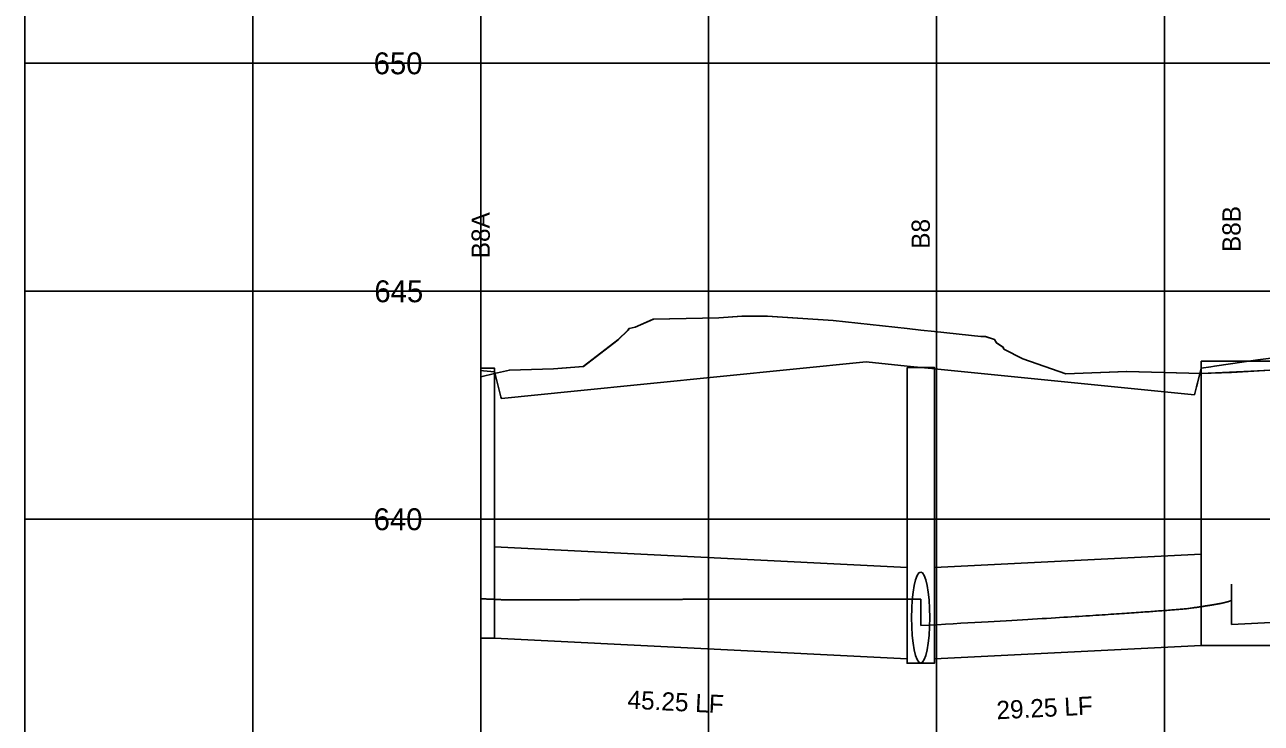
# Model space of a CAD drawing. Extents: x 2254979 to 2278074, y 13790855 to 13792793.
# Drawn here: x 2277749.4 to 2277885, y 13792568.9 to 13792645.5 of the extents above; entities that cross this region are included whole.
import ezdxf

# ---------------------------------------------------------------- set-up
doc = ezdxf.new("R2010")
doc.units = 0
for name, color, linetype in [('blank4', 7, 'Continuous'), ('BORD_grid_bottom_major_5int', 7, 'Continuous'), ('D_DRN_PROF_HGL', 7, 'Continuous'), ('D_PROF_1', 7, 'Continuous'), ('D_PROF_NOTES_1', 7, 'Continuous'), ('Default', 7, 'Continuous'), ('Drain_PipeInside', 7, 'Continuous'), ('E_Terrain', 7, 'Continuous'), ('Inlet', 7, 'Continuous'), ('z - Construction', 7, 'Continuous')]:
    doc.layers.add(name, color=color, linetype=linetype)

msp = doc.modelspace()

# ---------------------------------------------------------------- linework, layer by layer
at = {"layer": 'blank4'}
msp.add_lwpolyline([(2277799.4, 13792541.27), (2277799.4, 13792641.27), (2277979.76, 13792641.27), (2277979.76, 13792541.27)], close=True, dxfattribs=at)
at = {"layer": 'BORD_grid_bottom_major_5int'}
for p, q in [((2277749.4, 13792491.27), (2277749.4, 13792791.27)), ((2277774.4, 13792491.27), (2277774.4, 13792791.27)), ((2277799.4, 13792491.27), (2277799.4, 13792791.27)), ((2277824.4, 13792491.27), (2277824.4, 13792791.27)), ((2277849.4, 13792491.27), (2277849.4, 13792791.27)), ((2277874.4, 13792491.27), (2277874.4, 13792791.27)), ((2277749.4, 13792641.27), (2278074.4, 13792641.27)), ((2277749.4, 13792616.27), (2278074.4, 13792616.27)), ((2277749.4, 13792591.27), (2278074.4, 13792591.27))]:
    msp.add_line(p, q, dxfattribs=at)
at = {"layer": 'D_DRN_PROF_HGL'}
for p, q in [((2277881.73, 13792584.14), (2277881.73, 13792579.73)), ((2277847.65, 13792582.52), (2277847.65, 13792579.61))]:
    msp.add_line(p, q, dxfattribs=at)
for points in [[(2277847.65, 13792579.61), (2277848.55, 13792579.66), (2277849.47, 13792579.71), (2277850.36, 13792579.76), (2277851.22, 13792579.81), (2277852.04, 13792579.86), (2277852.83, 13792579.9), (2277853.59, 13792579.94), (2277854.32, 13792579.99), (2277855.03, 13792580.03), (2277855.72, 13792580.07), (2277856.38, 13792580.1), (2277857.02, 13792580.14), (2277857.63, 13792580.18), (2277858.23, 13792580.21), (2277858.81, 13792580.25), (2277859.38, 13792580.28), (2277859.92, 13792580.31), (2277860.45, 13792580.34), (2277860.97, 13792580.37), (2277861.46, 13792580.4), (2277861.95, 13792580.43), (2277862.42, 13792580.46), (2277862.88, 13792580.49), (2277863.33, 13792580.52), (2277863.76, 13792580.54), (2277864.19, 13792580.57), (2277864.6, 13792580.6), (2277865, 13792580.62), (2277865.39, 13792580.64), (2277865.77, 13792580.67), (2277866.15, 13792580.69), (2277866.51, 13792580.72), (2277866.86, 13792580.74), (2277867.21, 13792580.76), (2277867.55, 13792580.78), (2277867.88, 13792580.8), (2277868.2, 13792580.83), (2277868.51, 13792580.85), (2277868.82, 13792580.87), (2277869.12, 13792580.89), (2277869.41, 13792580.91), (2277869.7, 13792580.93), (2277869.98, 13792580.94), (2277870.25, 13792580.96), (2277870.52, 13792580.98), (2277870.78, 13792581), (2277871.04, 13792581.02), (2277871.29, 13792581.03), (2277871.54, 13792581.05), (2277871.78, 13792581.07), (2277872.01, 13792581.09), (2277872.24, 13792581.1), (2277872.47, 13792581.12), (2277872.69, 13792581.13), (2277872.9, 13792581.15), (2277873.11, 13792581.17), (2277873.32, 13792581.18), (2277873.52, 13792581.2), (2277873.72, 13792581.21), (2277873.91, 13792581.23), (2277874.1, 13792581.24), (2277874.29, 13792581.25), (2277874.47, 13792581.27), (2277874.65, 13792581.28), (2277874.83, 13792581.3), (2277875, 13792581.31), (2277875.17, 13792581.32), (2277875.33, 13792581.34), (2277875.49, 13792581.35), (2277875.65, 13792581.36), (2277875.81, 13792581.38), (2277875.96, 13792581.39), (2277876.11, 13792581.4), (2277876.25, 13792581.41), (2277876.39, 13792581.42), (2277876.53, 13792581.44), (2277876.67, 13792581.45), (2277876.81, 13792581.46), (2277876.94, 13792581.47), (2277877.07, 13792581.49), (2277877.19, 13792581.51), (2277877.32, 13792581.53), (2277877.44, 13792581.54), (2277877.56, 13792581.56), (2277877.67, 13792581.58), (2277877.79, 13792581.59), (2277877.9, 13792581.61), (2277878.01, 13792581.63), (2277878.11, 13792581.64), (2277878.22, 13792581.66), (2277878.32, 13792581.67), (2277878.42, 13792581.69), (2277878.52, 13792581.7), (2277878.62, 13792581.72), (2277878.71, 13792581.73), (2277878.8, 13792581.75), (2277878.89, 13792581.76), (2277878.98, 13792581.77), (2277879.07, 13792581.79), (2277879.15, 13792581.8), (2277879.24, 13792581.81), (2277879.32, 13792581.83), (2277879.4, 13792581.84), (2277879.47, 13792581.85), (2277879.55, 13792581.86), (2277879.62, 13792581.88), (2277879.7, 13792581.89), (2277879.77, 13792581.9), (2277879.84, 13792581.91), (2277879.9, 13792581.93), (2277879.97, 13792581.94), (2277880.03, 13792581.95), (2277880.1, 13792581.96), (2277880.16, 13792581.97), (2277880.22, 13792581.98), (2277880.28, 13792581.99), (2277880.33, 13792582), (2277880.39, 13792582.01), (2277880.44, 13792582.02), (2277880.5, 13792582.03), (2277880.55, 13792582.04), (2277880.6, 13792582.05), (2277880.65, 13792582.06), (2277880.69, 13792582.07), (2277880.74, 13792582.08), (2277880.78, 13792582.09), (2277880.83, 13792582.1), (2277880.87, 13792582.11), (2277880.91, 13792582.12), (2277880.95, 13792582.13), (2277880.99, 13792582.14), (2277881.03, 13792582.15), (2277881.07, 13792582.16), (2277881.1, 13792582.17), (2277881.14, 13792582.17), (2277881.17, 13792582.18), (2277881.2, 13792582.19), (2277881.23, 13792582.2), (2277881.26, 13792582.21), (2277881.29, 13792582.21), (2277881.32, 13792582.22), (2277881.35, 13792582.23), (2277881.37, 13792582.24), (2277881.4, 13792582.24), (2277881.42, 13792582.25), (2277881.44, 13792582.26), (2277881.46, 13792582.27), (2277881.49, 13792582.27), (2277881.51, 13792582.28), (2277881.52, 13792582.29), (2277881.54, 13792582.29), (2277881.56, 13792582.3), (2277881.58, 13792582.31), (2277881.59, 13792582.31), (2277881.61, 13792582.32), (2277881.62, 13792582.33), (2277881.63, 13792582.33), (2277881.65, 13792582.34), (2277881.66, 13792582.35), (2277881.67, 13792582.35), (2277881.68, 13792582.36), (2277881.69, 13792582.36), (2277881.69, 13792582.37), (2277881.7, 13792582.37), (2277881.71, 13792582.38), (2277881.71, 13792582.39), (2277881.72, 13792582.39), (2277881.72, 13792582.4), (2277881.72, 13792582.4), (2277881.73, 13792582.41), (2277881.73, 13792582.41), (2277881.73, 13792582.42), (2277881.73, 13792582.42), (2277881.73, 13792584.14)], [(2277799.4, 13792582.95), (2277799.4, 13792582.55), (2277799.44, 13792582.55), (2277799.53, 13792582.55), (2277799.62, 13792582.54), (2277799.7, 13792582.54), (2277799.79, 13792582.54), (2277799.88, 13792582.53), (2277799.97, 13792582.53), (2277800.06, 13792582.52), (2277800.15, 13792582.52), (2277800.24, 13792582.52), (2277800.33, 13792582.51), (2277800.42, 13792582.51), (2277800.5, 13792582.5), (2277800.59, 13792582.5), (2277800.68, 13792582.5), (2277800.77, 13792582.49), (2277800.86, 13792582.49), (2277800.95, 13792582.49), (2277801.04, 13792582.48), (2277801.13, 13792582.48), (2277801.22, 13792582.47), (2277801.31, 13792582.47), (2277801.4, 13792582.47), (2277801.49, 13792582.46), (2277801.58, 13792582.46), (2277801.67, 13792582.45), (2277801.76, 13792582.45), (2277801.85, 13792582.45), (2277801.94, 13792582.44), (2277802.03, 13792582.44), (2277802.12, 13792582.43), (2277802.21, 13792582.43), (2277802.3, 13792582.43), (2277802.39, 13792582.42), (2277802.48, 13792582.42), (2277802.57, 13792582.42), (2277802.66, 13792582.42), (2277802.75, 13792582.42), (2277802.84, 13792582.42), (2277802.93, 13792582.42), (2277803.02, 13792582.42), (2277803.11, 13792582.42), (2277803.2, 13792582.42), (2277803.29, 13792582.43), (2277803.38, 13792582.43), (2277803.47, 13792582.43), (2277803.56, 13792582.43), (2277803.66, 13792582.43), (2277803.75, 13792582.43), (2277803.84, 13792582.43), (2277803.93, 13792582.43), (2277804.02, 13792582.43), (2277804.11, 13792582.43), (2277804.2, 13792582.43), (2277804.29, 13792582.43), (2277804.38, 13792582.43), (2277804.48, 13792582.43), (2277804.57, 13792582.43), (2277804.66, 13792582.43), (2277804.75, 13792582.43), (2277804.84, 13792582.43), (2277804.93, 13792582.43), (2277805.02, 13792582.43), (2277805.11, 13792582.43), (2277805.21, 13792582.43), (2277805.3, 13792582.44), (2277805.39, 13792582.44), (2277805.48, 13792582.44), (2277805.57, 13792582.44), (2277805.67, 13792582.44), (2277805.76, 13792582.44), (2277805.85, 13792582.44), (2277805.94, 13792582.44), (2277806.03, 13792582.44), (2277806.12, 13792582.44), (2277806.22, 13792582.44), (2277806.31, 13792582.44), (2277806.4, 13792582.44), (2277806.49, 13792582.44), (2277806.58, 13792582.44), (2277806.68, 13792582.44), (2277806.77, 13792582.44), (2277806.86, 13792582.44), (2277806.95, 13792582.44), (2277807.05, 13792582.44), (2277807.14, 13792582.44), (2277807.23, 13792582.44), (2277807.32, 13792582.44), (2277807.42, 13792582.44), (2277807.51, 13792582.44), (2277807.6, 13792582.45), (2277807.69, 13792582.45), (2277807.79, 13792582.45), (2277807.88, 13792582.45), (2277807.97, 13792582.45), (2277808.06, 13792582.45), (2277808.16, 13792582.45), (2277808.25, 13792582.45), (2277808.34, 13792582.45), (2277808.44, 13792582.45), (2277808.53, 13792582.45), (2277808.62, 13792582.45), (2277808.71, 13792582.45), (2277808.81, 13792582.45), (2277808.9, 13792582.45), (2277808.99, 13792582.45), (2277809.09, 13792582.45), (2277809.18, 13792582.45), (2277809.27, 13792582.45), (2277809.37, 13792582.45), (2277809.46, 13792582.45), (2277809.55, 13792582.45), (2277809.65, 13792582.45), (2277809.74, 13792582.45), (2277809.83, 13792582.45), (2277809.93, 13792582.45), (2277810.02, 13792582.45), (2277810.11, 13792582.45), (2277810.21, 13792582.45), (2277810.3, 13792582.46), (2277810.39, 13792582.46), (2277810.49, 13792582.46), (2277810.58, 13792582.46), (2277810.67, 13792582.46), (2277810.77, 13792582.46), (2277810.86, 13792582.46), (2277810.96, 13792582.46), (2277811.05, 13792582.46), (2277811.14, 13792582.46), (2277811.24, 13792582.46), (2277811.33, 13792582.46), (2277811.42, 13792582.46), (2277811.52, 13792582.46), (2277811.61, 13792582.46), (2277811.71, 13792582.46), (2277811.8, 13792582.46), (2277811.89, 13792582.46), (2277811.99, 13792582.46), (2277812.08, 13792582.46), (2277812.18, 13792582.46), (2277812.27, 13792582.46), (2277812.36, 13792582.46), (2277812.46, 13792582.46), (2277812.55, 13792582.46), (2277812.65, 13792582.46), (2277812.74, 13792582.46), (2277812.83, 13792582.46), (2277812.93, 13792582.46), (2277813.02, 13792582.46), (2277813.12, 13792582.46), (2277813.21, 13792582.46), (2277813.31, 13792582.46), (2277813.4, 13792582.47), (2277813.5, 13792582.47), (2277813.59, 13792582.47), (2277813.68, 13792582.47), (2277813.78, 13792582.47), (2277813.87, 13792582.47), (2277813.97, 13792582.47), (2277814.06, 13792582.47), (2277814.16, 13792582.47), (2277814.25, 13792582.47), (2277814.35, 13792582.47), (2277814.44, 13792582.47), (2277814.54, 13792582.47), (2277814.63, 13792582.47), (2277814.72, 13792582.47), (2277814.82, 13792582.47), (2277814.91, 13792582.47), (2277815.01, 13792582.47), (2277815.1, 13792582.47), (2277815.2, 13792582.47), (2277815.29, 13792582.47), (2277815.39, 13792582.47), (2277815.48, 13792582.47), (2277815.58, 13792582.47), (2277815.67, 13792582.47), (2277815.77, 13792582.47), (2277815.86, 13792582.47), (2277815.96, 13792582.47), (2277816.05, 13792582.47), (2277816.15, 13792582.47), (2277816.24, 13792582.47), (2277816.34, 13792582.47), (2277816.43, 13792582.47), (2277816.53, 13792582.47), (2277816.62, 13792582.47), (2277816.72, 13792582.47), (2277816.81, 13792582.47), (2277816.91, 13792582.47), (2277817, 13792582.47), (2277817.1, 13792582.48), (2277817.2, 13792582.48), (2277817.29, 13792582.48), (2277817.39, 13792582.48), (2277817.48, 13792582.48), (2277817.58, 13792582.48), (2277817.67, 13792582.48), (2277817.77, 13792582.48), (2277817.86, 13792582.48), (2277817.96, 13792582.48), (2277818.05, 13792582.48), (2277818.15, 13792582.48), (2277818.24, 13792582.48), (2277818.34, 13792582.48), (2277818.44, 13792582.48), (2277818.53, 13792582.48), (2277818.63, 13792582.48), (2277818.72, 13792582.48), (2277818.82, 13792582.48), (2277818.91, 13792582.48), (2277819.01, 13792582.48), (2277819.1, 13792582.48), (2277819.2, 13792582.48), (2277819.3, 13792582.48), (2277819.39, 13792582.48), (2277819.49, 13792582.48), (2277819.58, 13792582.48), (2277819.68, 13792582.48), (2277819.77, 13792582.48), (2277819.87, 13792582.48), (2277819.97, 13792582.48), (2277820.06, 13792582.48), (2277820.16, 13792582.48), (2277820.25, 13792582.48), (2277820.35, 13792582.48), (2277820.45, 13792582.48), (2277820.54, 13792582.48), (2277820.64, 13792582.48), (2277820.73, 13792582.48), (2277820.83, 13792582.48), (2277820.93, 13792582.48), (2277821.02, 13792582.48), (2277821.12, 13792582.48), (2277821.21, 13792582.48), (2277821.31, 13792582.48), (2277821.41, 13792582.48), (2277821.5, 13792582.48), (2277821.6, 13792582.49), (2277821.69, 13792582.49), (2277821.79, 13792582.49), (2277821.89, 13792582.49), (2277821.98, 13792582.49), (2277822.08, 13792582.49), (2277822.17, 13792582.49), (2277822.27, 13792582.49), (2277822.37, 13792582.49), (2277822.46, 13792582.49), (2277822.56, 13792582.49), (2277822.66, 13792582.49), (2277822.75, 13792582.49), (2277822.85, 13792582.49), (2277822.95, 13792582.49), (2277823.04, 13792582.49), (2277823.14, 13792582.49), (2277823.23, 13792582.49), (2277823.33, 13792582.49), (2277823.43, 13792582.49), (2277823.52, 13792582.49), (2277823.62, 13792582.49), (2277823.72, 13792582.49), (2277823.81, 13792582.49), (2277823.91, 13792582.49), (2277824.01, 13792582.49), (2277824.1, 13792582.49), (2277824.2, 13792582.49), (2277824.3, 13792582.49), (2277824.39, 13792582.49), (2277824.49, 13792582.49), (2277824.58, 13792582.49), (2277824.68, 13792582.49), (2277824.78, 13792582.49), (2277824.87, 13792582.49), (2277824.97, 13792582.49), (2277825.07, 13792582.49), (2277825.16, 13792582.49), (2277825.26, 13792582.49), (2277825.36, 13792582.49), (2277825.45, 13792582.49), (2277825.55, 13792582.49), (2277825.65, 13792582.49), (2277825.74, 13792582.49), (2277825.84, 13792582.49), (2277825.94, 13792582.49), (2277826.03, 13792582.49), (2277826.13, 13792582.49), (2277826.23, 13792582.49), (2277826.33, 13792582.49), (2277826.42, 13792582.49), (2277826.52, 13792582.49), (2277826.62, 13792582.49), (2277826.71, 13792582.49), (2277826.81, 13792582.49), (2277826.91, 13792582.49), (2277827, 13792582.49), (2277827.1, 13792582.5), (2277827.2, 13792582.5), (2277827.29, 13792582.5), (2277827.39, 13792582.5), (2277827.49, 13792582.5), (2277827.58, 13792582.5), (2277827.68, 13792582.5), (2277827.78, 13792582.5), (2277827.88, 13792582.5), (2277827.97, 13792582.5), (2277828.07, 13792582.5), (2277828.17, 13792582.5), (2277828.26, 13792582.5), (2277828.36, 13792582.5), (2277828.46, 13792582.5), (2277828.55, 13792582.5), (2277828.65, 13792582.5), (2277828.75, 13792582.5), (2277828.85, 13792582.5), (2277828.94, 13792582.5), (2277829.04, 13792582.5), (2277829.14, 13792582.5), (2277829.23, 13792582.5), (2277829.33, 13792582.5), (2277829.43, 13792582.5), (2277829.53, 13792582.5), (2277829.62, 13792582.5), (2277829.72, 13792582.5), (2277829.82, 13792582.5), (2277829.92, 13792582.5), (2277830.01, 13792582.5), (2277830.11, 13792582.5), (2277830.21, 13792582.5), (2277830.3, 13792582.5), (2277830.4, 13792582.5), (2277830.5, 13792582.5), (2277830.6, 13792582.5), (2277830.69, 13792582.5), (2277830.79, 13792582.5), (2277830.89, 13792582.5), (2277830.99, 13792582.5), (2277831.08, 13792582.5), (2277831.18, 13792582.5), (2277831.28, 13792582.5), (2277831.37, 13792582.5), (2277831.47, 13792582.5), (2277831.57, 13792582.5), (2277831.67, 13792582.5), (2277831.76, 13792582.5), (2277831.86, 13792582.5), (2277831.96, 13792582.5), (2277832.06, 13792582.5), (2277832.15, 13792582.5), (2277832.25, 13792582.5), (2277832.35, 13792582.5), (2277832.45, 13792582.5), (2277832.54, 13792582.5), (2277832.64, 13792582.5), (2277832.74, 13792582.5), (2277832.84, 13792582.5), (2277832.93, 13792582.5), (2277833.03, 13792582.5), (2277833.13, 13792582.5), (2277833.23, 13792582.5), (2277833.32, 13792582.5), (2277833.42, 13792582.5), (2277833.52, 13792582.5), (2277833.62, 13792582.5), (2277833.72, 13792582.5), (2277833.81, 13792582.5), (2277833.91, 13792582.5), (2277834.01, 13792582.5), (2277834.11, 13792582.5), (2277834.2, 13792582.5), (2277834.3, 13792582.51), (2277834.4, 13792582.51), (2277834.5, 13792582.51), (2277834.59, 13792582.51), (2277834.69, 13792582.51), (2277834.79, 13792582.51), (2277834.89, 13792582.51), (2277834.99, 13792582.51), (2277835.08, 13792582.51), (2277835.18, 13792582.51), (2277835.28, 13792582.51), (2277835.38, 13792582.51), (2277835.47, 13792582.51), (2277835.57, 13792582.51), (2277835.67, 13792582.51), (2277835.77, 13792582.51), (2277835.87, 13792582.51), (2277835.96, 13792582.51), (2277836.06, 13792582.51), (2277836.16, 13792582.51), (2277836.26, 13792582.51), (2277836.35, 13792582.51), (2277836.45, 13792582.51), (2277836.55, 13792582.51), (2277836.65, 13792582.51), (2277836.75, 13792582.51), (2277836.84, 13792582.51), (2277836.94, 13792582.51), (2277837.04, 13792582.51), (2277837.14, 13792582.51), (2277837.24, 13792582.51), (2277837.33, 13792582.51), (2277837.43, 13792582.51), (2277837.53, 13792582.51), (2277837.63, 13792582.51), (2277837.73, 13792582.51), (2277837.82, 13792582.51), (2277837.92, 13792582.51), (2277838.02, 13792582.51), (2277838.12, 13792582.51), (2277838.21, 13792582.51), (2277838.31, 13792582.51), (2277838.41, 13792582.51), (2277838.51, 13792582.51), (2277838.61, 13792582.51), (2277838.71, 13792582.51), (2277838.8, 13792582.51), (2277838.9, 13792582.51), (2277839, 13792582.51), (2277839.1, 13792582.51), (2277839.2, 13792582.51), (2277839.29, 13792582.51), (2277839.39, 13792582.51), (2277839.49, 13792582.51), (2277839.59, 13792582.51), (2277839.69, 13792582.51), (2277839.78, 13792582.51), (2277839.88, 13792582.51), (2277839.98, 13792582.51), (2277840.08, 13792582.51), (2277840.18, 13792582.51), (2277840.27, 13792582.51), (2277840.37, 13792582.51), (2277840.47, 13792582.51), (2277840.57, 13792582.51), (2277840.67, 13792582.51), (2277840.77, 13792582.51), (2277840.86, 13792582.51), (2277840.96, 13792582.51), (2277841.06, 13792582.51), (2277841.16, 13792582.51), (2277841.26, 13792582.51), (2277841.35, 13792582.51), (2277841.45, 13792582.51), (2277841.55, 13792582.51), (2277841.65, 13792582.51), (2277841.75, 13792582.51), (2277841.85, 13792582.51), (2277841.94, 13792582.51), (2277842.04, 13792582.51), (2277842.14, 13792582.51), (2277842.24, 13792582.51), (2277842.34, 13792582.51), (2277842.44, 13792582.51), (2277842.53, 13792582.51), (2277842.63, 13792582.51), (2277842.73, 13792582.51), (2277842.83, 13792582.51), (2277842.93, 13792582.51), (2277843.03, 13792582.51), (2277843.12, 13792582.51), (2277843.22, 13792582.51), (2277843.32, 13792582.51), (2277843.42, 13792582.51), (2277843.52, 13792582.51), (2277843.62, 13792582.51), (2277843.71, 13792582.51), (2277843.81, 13792582.51), (2277843.91, 13792582.51), (2277844.01, 13792582.51), (2277844.11, 13792582.51), (2277844.21, 13792582.51), (2277844.3, 13792582.51), (2277844.4, 13792582.51), (2277844.5, 13792582.51), (2277844.6, 13792582.51), (2277844.7, 13792582.51), (2277844.8, 13792582.51), (2277844.9, 13792582.52), (2277844.99, 13792582.52), (2277845.09, 13792582.52), (2277845.19, 13792582.52), (2277845.29, 13792582.52), (2277845.39, 13792582.52), (2277845.49, 13792582.52), (2277845.58, 13792582.52), (2277845.68, 13792582.52), (2277845.78, 13792582.52), (2277845.88, 13792582.52), (2277845.98, 13792582.52), (2277846.08, 13792582.52), (2277846.18, 13792582.52), (2277846.27, 13792582.52), (2277846.37, 13792582.52), (2277846.47, 13792582.52), (2277846.57, 13792582.52), (2277846.67, 13792582.52), (2277846.77, 13792582.52), (2277846.87, 13792582.52), (2277846.96, 13792582.52), (2277847.06, 13792582.52), (2277847.16, 13792582.52), (2277847.26, 13792582.52), (2277847.36, 13792582.52), (2277847.46, 13792582.52), (2277847.56, 13792582.52), (2277847.65, 13792582.52)], [(2277881.73, 13792579.73), (2277899.85, 13792580.63)]]:
    msp.add_lwpolyline(points, dxfattribs=at)
at = {"layer": 'D_PROF_1'}
msp.add_lwpolyline([(2277799.42, 13792607.58), (2277799.72, 13792607.55), (2277800.92, 13792607.43), (2277800.92, 13792607.43), (2277801.02, 13792607.03), (2277801.44, 13792605.41), (2277801.62, 13792604.7), (2277801.67, 13792604.52), (2277809.67, 13792605.32), (2277841.67, 13792608.52), (2277846.17, 13792608.07), (2277846.17, 13792608.07), (2277847.67, 13792607.92), (2277847.67, 13792607.92), (2277848.87, 13792607.8), (2277849.17, 13792607.77), (2277849.17, 13792607.77), (2277877.67, 13792604.92), (2277877.85, 13792605.63), (2277877.9, 13792605.81), (2277878, 13792606.21), (2277878.42, 13792607.83), (2277878.42, 13792607.83), (2277879.45, 13792607.98), (2277879.88, 13792608.05), (2277884.6, 13792608.74), (2277884.6, 13792608.74), (2277886.08, 13792608.93)], dxfattribs=at)
at = {"layer": 'Drain_PipeInside'}
for p, q in [((2277800.9, 13792588.23), (2277846.15, 13792585.97)), ((2277849.15, 13792585.98), (2277878.41, 13792587.44)), ((2277800.9, 13792578.23), (2277846.15, 13792575.97)), ((2277849.15, 13792575.98), (2277878.41, 13792577.44))]:
    msp.add_line(p, q, dxfattribs=at)
msp.add_ellipse((2277847.65, 13792580.48), major_axis=(0, 5), ratio=0.2, dxfattribs=at)
at = {"layer": 'E_Terrain'}
for points in [[(2277799.4, 13792606.88), (2277800.9, 13792607.24), (2277800.9, 13792607.24), (2277802.55, 13792607.63), (2277807.37, 13792607.77), (2277810.65, 13792608.03), (2277814.45, 13792610.93), (2277815.55, 13792612), (2277815.67, 13792612.2), (2277816.34, 13792612.35), (2277818.33, 13792613.2), (2277825.52, 13792613.36), (2277828.05, 13792613.53), (2277829.81, 13792613.54), (2277830.25, 13792613.53), (2277830.32, 13792613.53), (2277830.83, 13792613.53), (2277838.06, 13792613.05), (2277846.15, 13792612.18), (2277846.15, 13792612.18), (2277847.65, 13792612.02), (2277847.65, 13792612.02), (2277849.15, 13792611.86), (2277849.15, 13792611.86), (2277854.24, 13792611.31), (2277854.72, 13792611.33), (2277855.74, 13792610.99), (2277855.97, 13792610.61), (2277856.67, 13792610.16), (2277856.75, 13792609.93), (2277858.84, 13792608.86), (2277863.57, 13792607.23), (2277870.23, 13792607.47), (2277878.41, 13792607.26), (2277878.41, 13792607.26), (2277881.73, 13792607.38), (2277881.73, 13792607.38), (2277887.23, 13792607.69)], [(2277799.42, 13792606.88), (2277800.92, 13792607.24), (2277800.92, 13792607.24), (2277802.56, 13792607.63), (2277807.39, 13792607.77), (2277810.66, 13792608.03), (2277814.46, 13792610.93), (2277815.56, 13792612), (2277815.69, 13792612.2), (2277816.35, 13792612.35), (2277818.35, 13792613.2), (2277825.53, 13792613.36), (2277828.06, 13792613.53), (2277829.82, 13792613.54), (2277830.26, 13792613.53), (2277830.33, 13792613.53), (2277830.84, 13792613.53), (2277838.07, 13792613.05), (2277846.17, 13792612.18), (2277846.17, 13792612.18), (2277847.67, 13792612.02), (2277847.67, 13792612.02), (2277849.17, 13792611.86), (2277849.17, 13792611.86), (2277854.25, 13792611.31), (2277854.74, 13792611.33), (2277855.75, 13792610.99), (2277855.98, 13792610.61), (2277856.68, 13792610.16), (2277856.76, 13792609.93), (2277858.85, 13792608.86), (2277863.58, 13792607.23), (2277870.24, 13792607.47), (2277878.42, 13792607.26), (2277878.42, 13792607.26), (2277884.6, 13792607.55), (2277884.6, 13792607.55), (2277893.1, 13792608.02)]]:
    msp.add_lwpolyline(points, dxfattribs=at)
at = {"layer": 'Inlet'}
for points in [[(2277878.41, 13792608.59), (2277887.23, 13792608.59), (2277887.23, 13792577.44), (2277878.41, 13792577.44)], [(2277799.4, 13792607.85), (2277800.9, 13792607.85), (2277800.9, 13792578.23), (2277799.4, 13792578.23)], [(2277846.15, 13792607.92), (2277849.15, 13792607.92), (2277849.15, 13792575.48), (2277846.15, 13792575.48)]]:
    msp.add_lwpolyline(points, close=True, dxfattribs=at)
at = {"layer": 'z - Construction'}
for p, q in [((2277799.4, 13792616.27), (2277979.76, 13792616.27)), ((2277799.4, 13792591.27), (2277979.76, 13792591.27))]:
    msp.add_line(p, q, dxfattribs=at)

# ---------------------------------------------------------------- texts
at = {"layer": 'D_PROF_NOTES_1'}
for s, rotation, p in [('B8A', 90, (2277800.4, 13792619.89)), ('B8B', 90, (2277882.73, 13792620.57)), ('B8', 90, (2277848.65, 13792620.93)), ('45.25 LF', 357.1376, (2277815.46, 13792570.51)), ('29.25 LF', 2.8624, (2277856.01, 13792569.33))]:
    msp.add_text(s, height=2, rotation=rotation, dxfattribs=at).set_placement(p)
at = {"layer": 'Default'}
for s, p in [('650', (2277787.66, 13792640.07)), ('645', (2277787.74, 13792615.07)), ('640', (2277787.66, 13792590.07))]:
    msp.add_text(s, height=2.4, dxfattribs=at).set_placement(p)

doc.saveas('drawing.dxf')
